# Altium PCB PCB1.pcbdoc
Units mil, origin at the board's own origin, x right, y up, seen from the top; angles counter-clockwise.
Board outline 6751.1 x 3505.43 mil, 4 copper layers (Top Layer, Inner1, Inner2, Bottom Layer); 50 components, 35 nets, 178 pads, 64 vias.
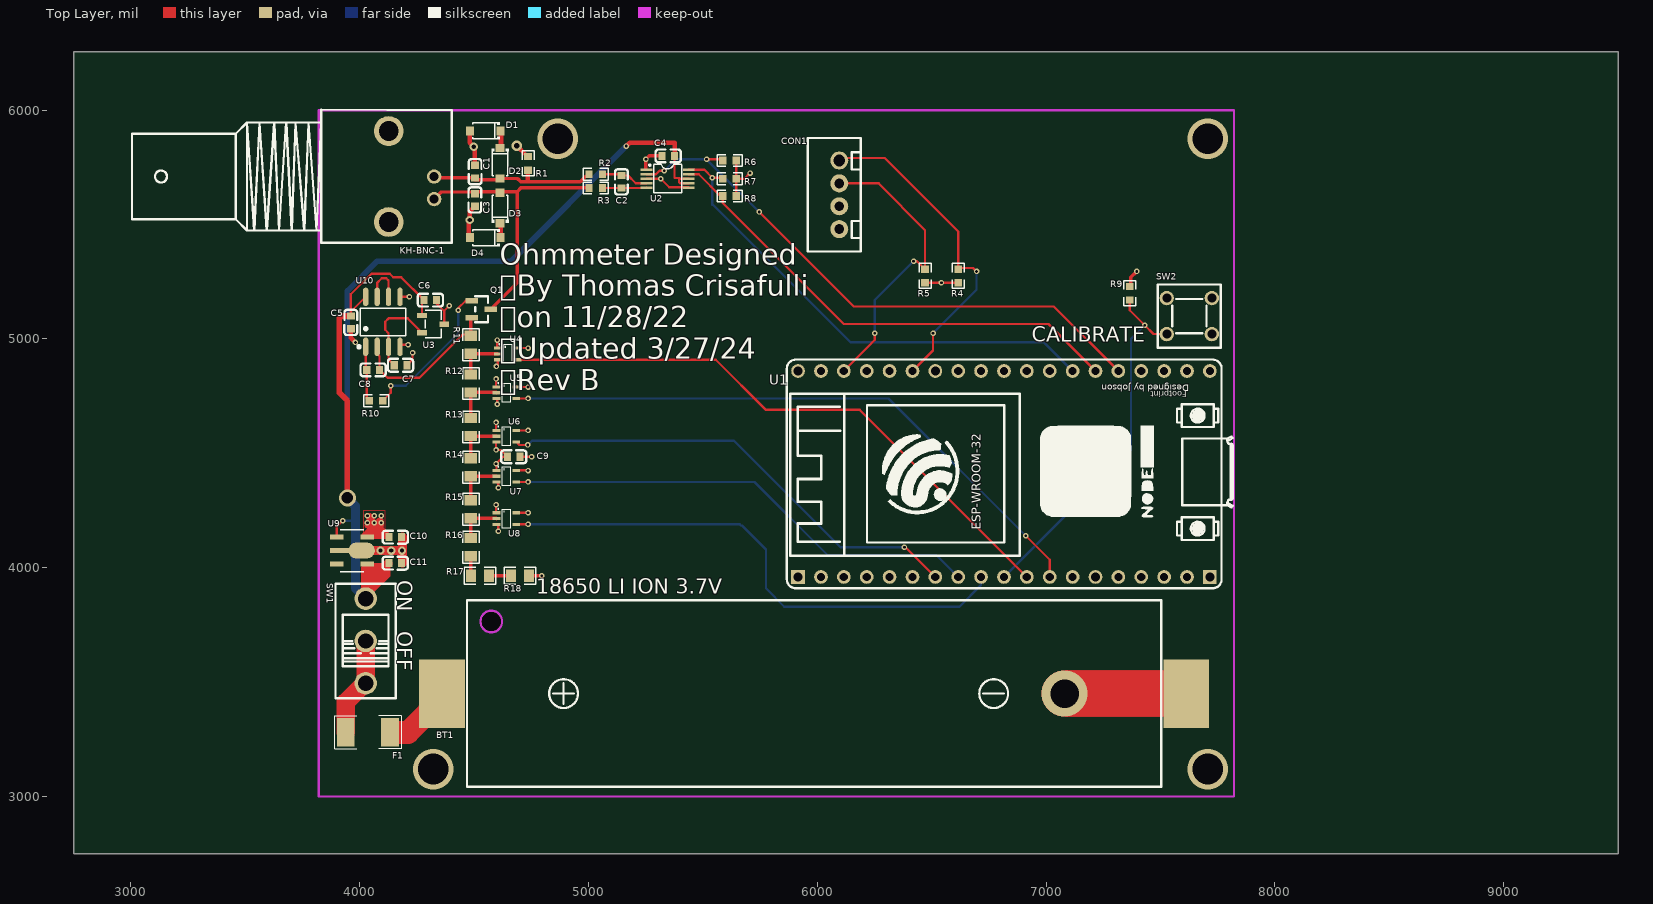
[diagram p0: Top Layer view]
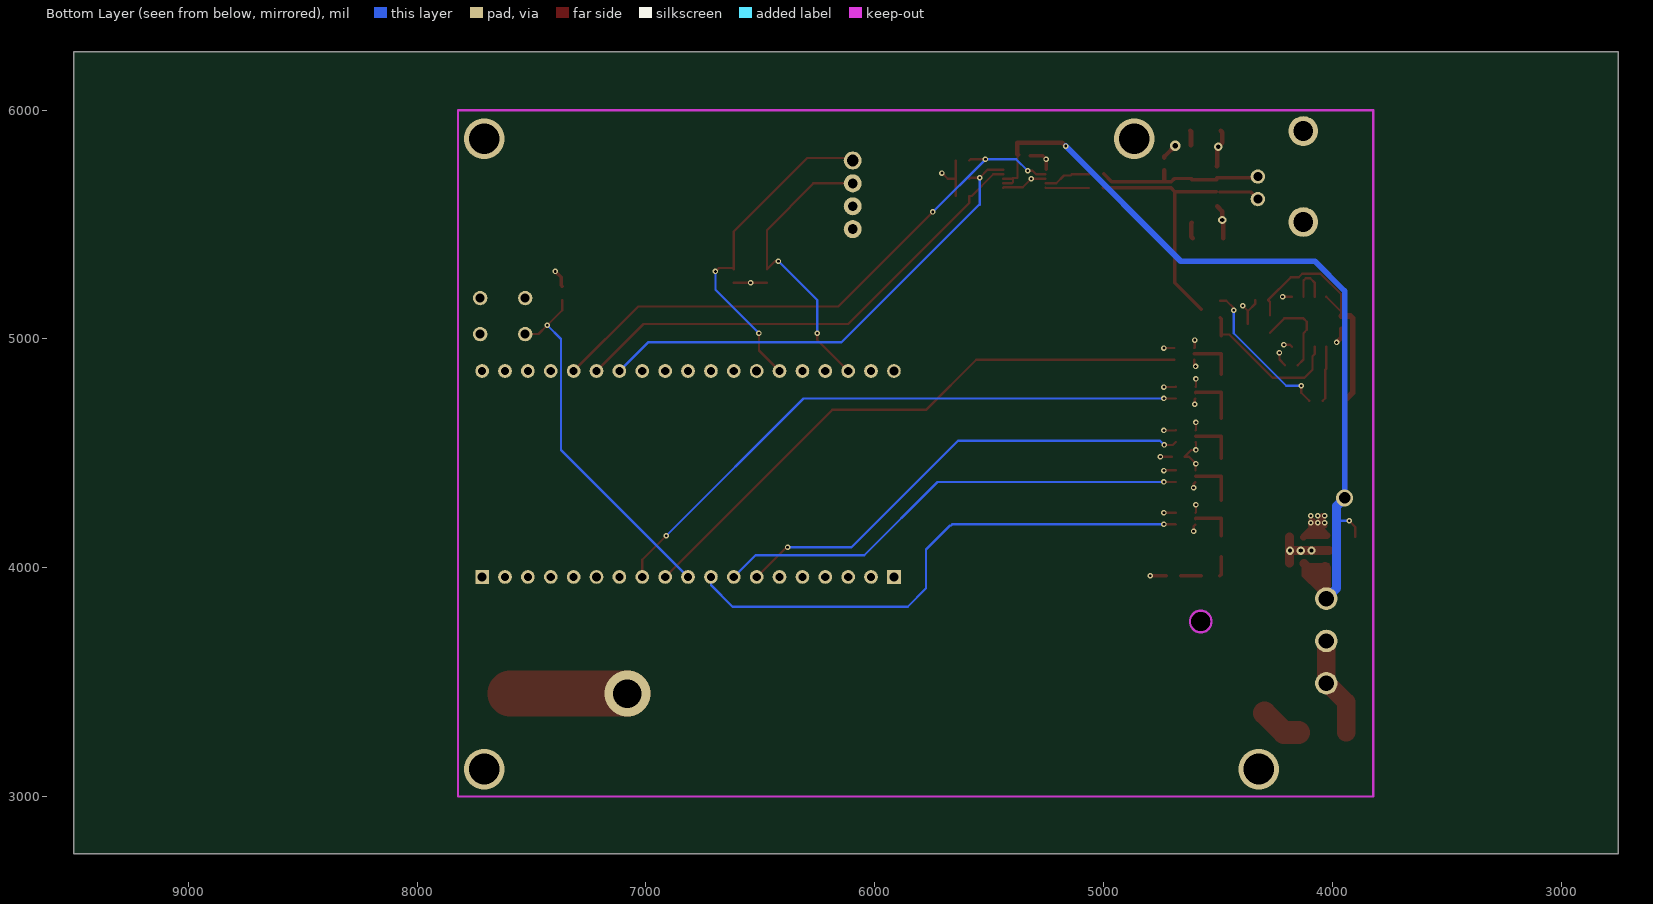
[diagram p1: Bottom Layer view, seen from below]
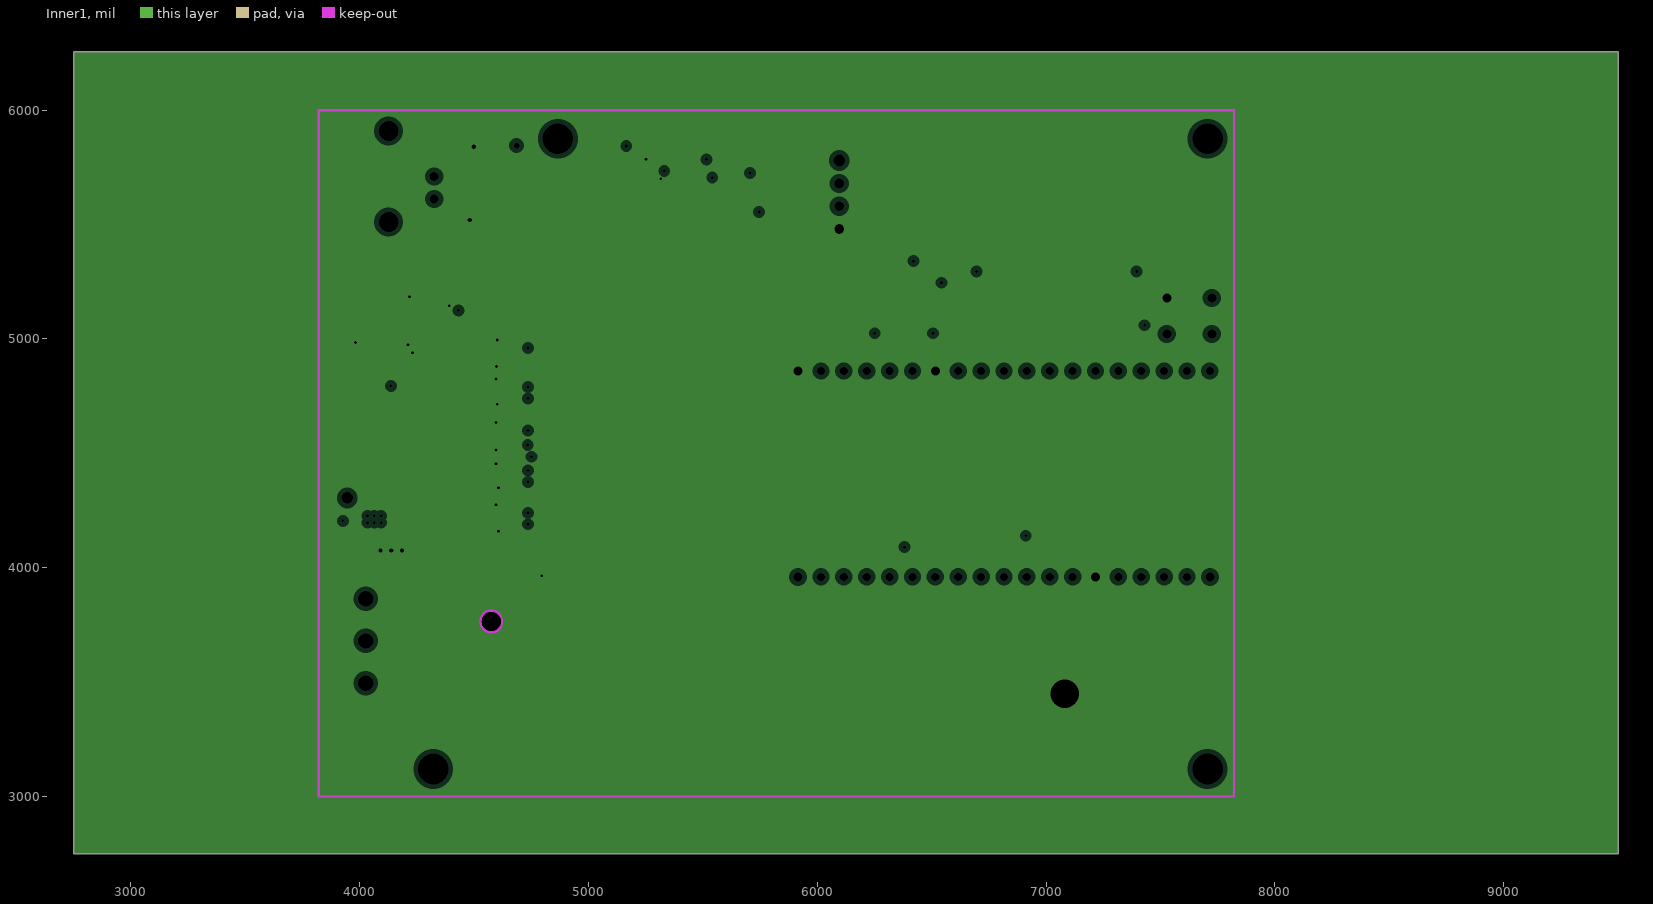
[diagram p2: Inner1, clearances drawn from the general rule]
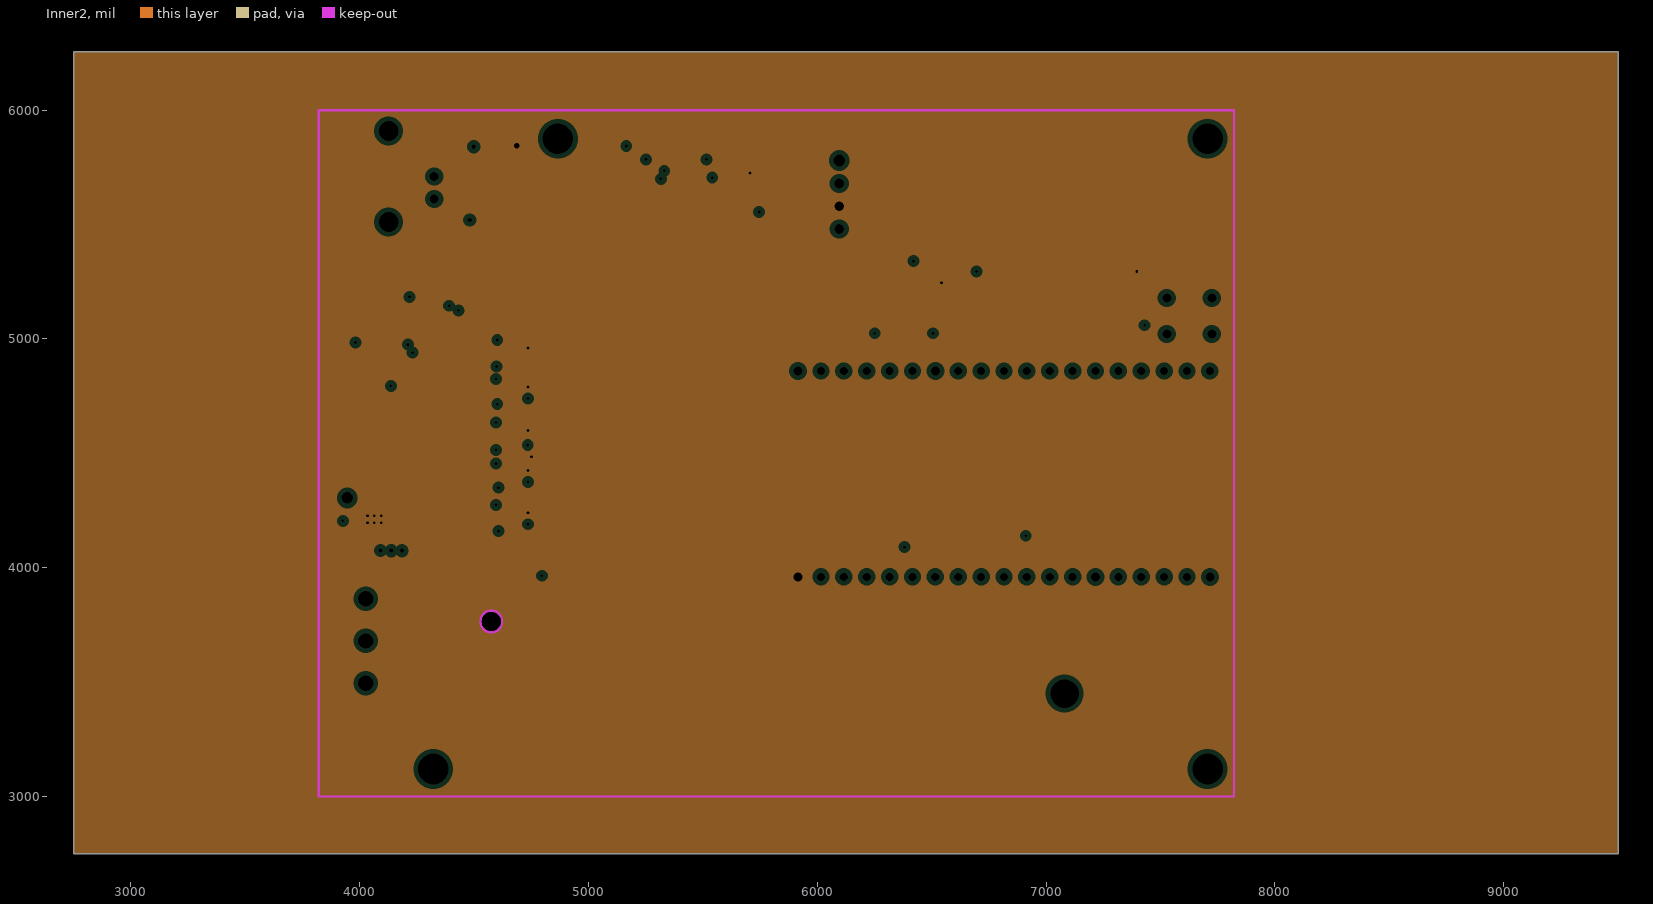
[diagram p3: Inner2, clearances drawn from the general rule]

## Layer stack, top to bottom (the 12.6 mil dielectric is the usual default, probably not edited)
Top Layer: signal copper (thickness not stored)
Dielectric: dielectric 12.6, FR-4, Dk 4.8
Inner1: plane copper (thickness not stored)
Dielectric: dielectric 12.6, FR-4, Dk 4.8
Inner2: plane copper (thickness not stored)
Dielectric: dielectric 12.6, FR-4, Dk 4.8
Bottom Layer: signal copper (thickness not stored)

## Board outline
9501.1,2750 2750,2750 2750,6255.43 9501.1,6255.43

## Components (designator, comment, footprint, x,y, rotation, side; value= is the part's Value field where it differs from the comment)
BT1 "BH-18650-B1BA002" BATTERY-SMD_18650-1S-L77.1-W20.7-1 5986.1,3450 r90 top
C1 "06031C103K4T2A" C0603 4504.6,5731.44 r90 top
C2 "CC0603KRX7R9BB104" C0603 5144.1,5687 r90 top
C3 "06031C103K4T2A" C0603 4503.6,5607.44 r270 top
C4 "CC0603KRX7R9BB104" C0603 5348.54,5800 r0 top
C5 "CC0603KRX7R9BB104" C0603 3961.1,5072.44 r90 top
C6 "CL10A106KP8NNNC" C0603 4308.54,5170 r180 top
C7 "CC0603KRX7R9BB104" C0603 4178.66,4885 r0 top
C8 "0603CG101F500NT" C0603 4058.66,4865 r0 top
C9 "CC0603KRX7R9BB104" C0603 4673.66,4485 r0 top
C10 "CL10A106KP8NNNC" C0603 4155.37,4133.54 r180 top
C11 "CL10A106KP8NNNC" C0603 4155.13,4020 r180 top
CON1 "XH2.54-4_C9900012082" CONN-TH_XH2.54-4 6096.1,5630 r90 top
D1 "PTVS30VS1UR,115" SOD-123_L2.6-W1.7-LS3.5-RD 4548.6,5910 r180 top
D2 "PTVS30VS1UR,115" SOD-123_L2.6-W1.7-LS3.5-RD 4613.6,5768 r270 top
D3 "PTVS30VS1UR,115" SOD-123_L2.6-W1.7-LS3.5-RD 4613.6,5572.5 r90 top
D4 "PTVS30VS1UR,115" SOD-123_L2.6-W1.7-LS3.5-RD 4548.6,5442.5 r180 top
F1 "0451.400MRL" 0451.400MRL 4171.1,3280 r180 top
KH-BNC-1 "KH-BNC75-3511" ANT-TH_KH-BNC75-3511 4226.1,5710 r270 top
Q1 "BSH105,215" TO-236AB_L2.9-W1.3-P0.95-LS2.3-BR 4531.1,5130 r180 top
R1 "AC0603FR-0710RL" R0603 4736.1,5767.5 r90 top
R2 "RS-03K2700FT" R0603 5031.44,5720 r0 top
R3 "RS-03K2700FT" R0603 5031.44,5660 r0 top
R4 "RMC06035.6K1%N" R0603 6616.1,5275.34 r90 top
R5 "RMC06035.6K1%N" R0603 6471.1,5275.34 r270 top
R6 "RMC06035.6K1%N" R0603 5616.44,5780 r0 top
R7 "RMC06035.6K1%N" R0603 5616.44,5700 r0 top
R8 "RMC06035.6K1%N" R0603 5616.44,5625 r0 top
R9 "RMC06035.6K1%N" R0603 7366.1,5199.66 r90 top
R10 "RMC06035.6K1%N" R0603 4071.44,4730 r180 top
R11 "RT0805BRB07100RL" R0805 4486.1,4974.37 r90 top
R12 "PTFR0805B620RN9" R0805 4486.1,4805 r90 top
R13 "PTFR0805B3K30N9" R0805 4486.1,4615 r90 top
R14 "PTFR0805B22K0N9" R0805 4486.1,4439.37 r90 top
R15 "PTFR0805B130KN9" R0805 4486.1,4255.63 r90 top
R16 "PTFR0805B270KN9" R0805 4486.1,4090 r90 top
R17 "PTFR0805B270KN9" R0805 4526.1,3965 r180 top
R18 "PTFR0805B270KN9" R0805 4701.1,3965 r180 top
SW1 "SS-12D10L4" SW-TH_SS-12D10L3 4026.1,3680 r90 top
SW2 "BTSA-N-P-11" SW-TH_BTSA-X-P-11 7626.1,5100 r0 top
U1 "ESP32" NODEMCU-32SLUA 6816.1,4410 r90 top
U2 "ADS1115IDGST" VSSOP-10_L3.0-W3.0-P0.50-LS4.9-BL 5346.1,5700 r270 top
U3 "REF3112AIDBZR" SOT-23-3_L2.9-W1.6-P1.90-LS2.8-BR 4321.1,5065 r180 top
U4 "MAX4715EXK+T" SC-70-5_L2.0-W1.3-P0.65-LS2.1-BR 4646.1,4935 r180 top
U5 "MAX4715EXK+T" SC-70-5_L2.0-W1.3-P0.65-LS2.1-BR 4641.1,4765 r180 top
U6 "MAX4715EXK+T" SC-70-5_L2.0-W1.3-P0.65-LS2.1-BR 4641.1,4575 r180 top
U7 "MAX4715EXK+T" SC-70-5_L2.0-W1.3-P0.65-LS2.1-BR 4641.1,4400 r180 top
U8 "MAX4715EXK+T" SC-70-5_L2.0-W1.3-P0.65-LS2.1-BR 4641.1,4215 r180 top
U9 "ME6217C33P5G" SOT-89-5_L4.5-W2.5-P1.50-LS4.5-BR 3966.1,4075 r180 top
U10 "OPA2365AIDR" SOIC-8_L4.9-W3.9-P1.27-LS6.0-BL 4101.1,5075 r0 top

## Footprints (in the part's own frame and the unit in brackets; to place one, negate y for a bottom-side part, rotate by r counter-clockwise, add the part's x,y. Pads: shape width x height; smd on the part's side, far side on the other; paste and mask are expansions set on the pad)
0451.400MRL [mm]
  rect 1.96x3.16 smd: 1(0.98,0) 2(5.89,0)
  silkscreen extent -0.26,-1.83 7.13,1.83
ANT-TH_KH-BNC75-3511 [mm]
  round 1.6 hole 1: 1(0,2.525) 2(2.5,2.525)
  round 3.3 hole 2.2: 3(5.05,-2.525) 4(-5.05,-2.525)
  silkscreen extent -7.44,-31.02 7.35,4.47
BATTERY-SMD_18650-1S-L77.1-W20.7-1 [mil]
  rect 300x200 smd: 1(0,-1626.5) 2(0,1626.5)
  Multi-Layer board cut-out: 314.96,1363.78 338.42,1370.23 355.56,1387.51 361.83,1411.02 355.56,1434.53 338.42,1451.81 314.96,1458.26 314.96,1458.26 291.5,1451.81 274.36,1434.53 268.09,1411.02 274.36,1387.51 291.5,1370.23 314.96,1363.78
  silkscreen extent -408,-1518 408,1518
C0603 [mm]
  rect 0.8x0.9 smd: 1(-0.7,0) 2(0.7,0)
  silkscreen extent -1.41,-0.71 1.39,0.72
CONN-TH_XH2.54-4 [mm]
  round 2 hole 1.1: 1(-3.81,0) 2(-1.27,0) 3(1.27,0)
  round 2 hole 1.3: 4(3.81,0)
  silkscreen extent -6.3,-2.4 6.3,3.5
NODEMCU-32SLUA [mil]
  rect 60x60 hole 39.37: 1(-450,-900) 19(-450,900)
  round 60 hole 36: 2(-450,-800) 3(-450,-700) 4(-450,-600) 5(-450,-500) 7(-450,-300) 8(-450,-200) 9(-450,-100) 10(-450,0) 11(-450,100) 12(-450,200) 13(-450,300) 14(-450,400) 15(-450,500) 16(-450,600) 17(-450,700) 18(-450,800) 20(450,-900) 21(450,-800) 22(450,-700) 23(450,-600) 24(450,-500) 25(450,-400) 26(450,-300) 27(450,-200) 28(450,-100) 29(450,0) 30(450,100) 31(450,200) 33(450,400) 34(450,500) 35(450,600) 36(450,700) 37(450,800)
  round 60 hole 39.37: 6(-450,-400) 32(450,300) 38(450,900)
  silkscreen extent -500,-999 500,949
R0603 [mil]
  rect 31.75x34.02 smd: 1(-29.66,0) 2(29.66,0)
  silkscreen extent -55,-26 55,26
R0805 [mm]
  rect 1.133x1.377 smd: 1(-1,0) 2(1,0)
  silkscreen extent -1.76,-0.92 1.76,0.92
SC-70-5_L2.0-W1.3-P0.65-LS2.1-BR [mm]
  rect 0.85x0.35 smd: 1(1.1,-0.65) 2(1.1,0) 3(1.1,0.65) 4(-1.1,0.65) 5(-1.1,-0.65)
  silkscreen extent -0.5,-1.12 0.96,1
SOD-123_L2.6-W1.7-LS3.5-RD [mm]
  rect 0.9x1 smd: 1(-1.692,0) 2(1.692,0)
  silkscreen extent -1.63,-0.94 1.41,0.94
SOIC-8_L4.9-W3.9-P1.27-LS6.0-BL [mm]
  oval 0.588x2.045 smd: 1(-1.905,-2.772) 2(-0.635,-2.772) 3(0.635,-2.772) 4(1.905,-2.772) 5(1.905,2.772) 6(0.635,2.772) 7(-0.635,2.772) 8(-1.905,2.772)
  silkscreen extent -2.8,-2.92 2.53,1.52
SOT-23-3_L2.9-W1.6-P1.90-LS2.8-BR [mm]
  rect 1.07x0.6 smd: 1(1.235,-0.95) 2(1.235,0.95) 3(-1.235,0)
  silkscreen extent -0.88,-1.54 0.88,1.54
SOT-89-5_L4.5-W2.5-P1.50-LS4.5-BR [mm]
  rect 1.5x0.574 smd: 1(1.697,-1.5) 3(1.697,1.5) 4(-1.697,1.5) 5(-1.697,-1.5)
  oval 2.94x1.76 smd: 2(-1.068,0)
  rect 2.209x0.552 smd: 2(1.343,0)
  silkscreen extent -1.3,-2.33 1.3,2.33
SW-TH_BTSA-X-P-11 [mm]
  round 1.6 hole 1: 1(-2.5,2) 2(-2.5,-2) 3(2.5,2) 4(2.5,-2)
  silkscreen extent -3.5,-3.5 3.5,3.5
SW-TH_SS-12D10L3 [mm]
  round 2.5 hole 1.7: 1(-4.7,0) 2(0,0) 3(4.7,0)
  silkscreen extent -6.35,-3.35 6.35,3.35
TO-236AB_L2.9-W1.3-P0.95-LS2.3-BR [mm]
  rect 1.4x0.6 smd: 1(1.05,-0.95) 2(1.05,0.95) 3(-1.05,0)
  silkscreen extent -0.75,-1.45 0.65,1.45
VSSOP-10_L3.0-W3.0-P0.50-LS4.9-BL [mm]
  rect 0.3x1.3 smd: 1(-1,-2.35) 2(-0.5,-2.35) 3(0,-2.35) 4(0.5,-2.35) 5(1,-2.35) 6(1,2.35) 7(0.5,2.35) 8(0,2.35) 9(-0.5,2.35) 10(-1,2.35)
  silkscreen extent -1.62,-2.08 1.52,1.54

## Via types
v1: diameter 24.02, hole 12.01, Top Layer to Bottom Layer, 42 vias
v2: diameter 24, hole 12, Top Layer to Bottom Layer, 10 vias
v3: diameter 36, hole 18, Top Layer to Bottom Layer, 5 vias
v4: diameter 177, hole 134, Top Layer to Bottom Layer, 4 vias
v5: diameter 75, hole 50, Top Layer to Bottom Layer, 1 vias
v6: diameter 200, hole 125, Top Layer to Bottom Layer, 1 vias
v7: diameter 45, hole 25, Top Layer to Bottom Layer, 1 vias

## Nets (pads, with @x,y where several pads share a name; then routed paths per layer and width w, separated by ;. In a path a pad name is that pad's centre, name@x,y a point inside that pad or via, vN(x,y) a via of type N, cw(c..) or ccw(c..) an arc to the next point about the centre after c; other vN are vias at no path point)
1.250V: C7.1 U3.2 U10.3 | length 400
  Top Layer w10: C7.1 4126.1,4910 U10.3 4126.1,5025 4111.1,5040 4111.1,5075 4126.1,5090 4210.08,5090 U3.2
3V3: C9.2 C10.2 CON1.2 R1.2 R4.1 R5.2 R6.2 R7.2 R8.2 R9.2 U1.19 U4.5 U5.5 U6.5 U7.5 U8.5 U9.5 | length 1248.4
  Top Layer w10: U8.5 4685,4240 v1(4736.1,4240) ; U7.5 4735.51,4425.59 v1(4736.1,4425) ; U6.5 4685,4600 v1(4736.1,4600) ; U5.5 4685,4790 v1(4736.1,4790) ; U4.5 4735.51,4960.59 v1(4736.1,4960) ; C9.2 v1(4751.1,4485) ; R8.2 R7.2 ; R6.2 R7.2 ; v1(5706.1,5725) 5681.1,5700 R7.2 ; R5.2 v1(6542.96,5245.68) R4.1
  Top Layer w15: R9.2 7371.1,5234.32 7371.1,5270 v1(7396.1,5295)
  Top Layer w20: v7@4682.35,5848.75 4733.6,5797.5 R1.2@4733.6,5793.09
  Top Layer w25: 4033.6,4184.23 4046.1,4196.73 ; v1(4033.6,4196.73) 4046.1,4196.73 ; 4060.43,4152.4 4093.6,4185.57 v1(4093.6,4196.73) ; v1(4063.6,4196.73) 4051.1,4196.73 4048.6,4199.23 4046.1,4196.73
  Top Layer w30: U9.5@4023.69,4140.98 C10.2@4119.37,4140.98 ; U9.5@4033.78,4139.56 4033.78,4151.07 v1@4089.58,4206.87 ; v1@4043.6,4224.23 4043.6,4215.25 C10.2@4125.31,4133.54
  other v1: 4033.6,4226.73 4063.6,4226.73 4093.6,4226.73
  other v7: 4686.1,5845
$1N34949: D1.1 D2.1 | length 65
  Top Layer w20: D2.1@4618.6,5846.63 4617.47,5847.76 4617.47,5907.24 D1.1@4620.23,5910
$1N40044: D3.1 D4.1 | length 72.4
  Top Layer w20: D4.1@4610.23,5440 4616.77,5446.54 4616.77,5505.2 D3.1@4613.6,5508.37
$1N64285: C1.1 D2.2 KH-BNC-1.1 R1.1 R2.1 | length 736.4
  Top Layer w15: KH-BNC-1.1 4331.63,5703.88 C1.1 ; C1.1@4504.6,5695.43 D2.2@4613.6,5695.43 ; D2.2 4689.73,5701.37 4703.6,5687.5 4964.95,5687.5 R2.1@4998.7,5721.25
  Top Layer w20: 4733.6,5696.9 R1.1@4733.6,5737.84
$4N526: Q1.1 R10.1 | length 651.8
  Top Layer w10: R10.1 4136.1,4765 v2(4136.1,4795) ; v2(4431.1,5125) 4431.1,5135 4463.5,5167.4 Q1.1
  Bottom Layer w10: v2(4136.1,4795) 4201.1,4795 4431.1,5025 v2(4431.1,5125)
$4N529: C8.1 R10.2 U10.1 | length 242.3
  Top Layer w10: U10.1 4026.1,4870 C8.1 4031.1,4740.68 R10.2
$4N533: U10.6 U10.7 | length 194.1
  Top Layer w10: U10.7 4076.1,5245 4096.1,5265 4116.1,5265 4126.1,5255 U10.6
$4N538: C8.2 Q1.2 R11.2 U10.2 | length 680.5
  Top Layer w10: U10.2 4076.1,4935 4086.22,4924.88 C8.2 4121.22,4830 4261.1,4830 4450.42,5019.32 4480.52,5019.32 R11.2
  Top Layer w15: R11.2 4486.1,5088.94 Q1.2
$4N2969: R16.1 R17.2 | length 84.8
  Top Layer w15: R16.1@4486.1,4047.78 4486.1,3970 R17.2@4491.1,3965
$4N2970: R17.1 R18.2 | length 88.4
  Top Layer w15: R17.1@4573.33,3965 R18.2
$4N2972: R15.1 R16.2 U8.2 | length 188.5
  Top Layer w15: R16.2@4486.1,4140 R15.1 4596.53,4216.26 U8.2
$4N2973: R13.1 R14.2 U6.2 | length 208
  Top Layer w15: R14.2 4486.1,4575 U6.2
$4N2979: R14.1 R15.2 U7.2 | length 216.7
  Top Layer w15: R15.2 R14.1 U7.2
$4N2983: R12.1 R13.2 U5.2 | length 224.7
  Top Layer w15: R13.2@4486.1,4653.74 4486.1,4766.26 4596.53,4766.26 U5.2
$4N3047: R11.1 R12.2 U4.2 | length 206.7
  Top Layer w15: R12.2@4486.1,4845 R11.1 U4.2
$6N1642: BT1.2 F1.1 | length 183.8
  Top Layer w100: F1.1@4147.47,3280 4211.1,3280 BT1.2@4296.1,3365
$6N1643: F1.2 SW1.1 SW1.2 | length 435.6
  Top Layer w80: F1.2 3939.21,3413.04 4026.83,3500.66 SW1.2@4026.83,3679.27
ADC_AIN0: C2.2 R2.2 U2.4 | length 207.3
  Top Layer w10: R2.2@5062.74,5720 5138.66,5720 C2.2 5173.02,5714.56 5206.89,5680.69 5253.21,5680.69 U2.4
ADC_AIN1: C2.1 R3.2 U2.5 | length 191.4
  Top Layer w10: R3.2@5062.94,5660 5143.54,5660 C2.1 5252.4,5659.44 U2.5
ADC_I2C_ALERT_RDY: R6.1 U1.24 U2.2 | length 2545.5
  Top Layer w10: U2.2 5294.76,5719.69 5310.08,5735 v2(5331.1,5735) ; v2(5516.1,5785) 5581.78,5785 R6.1 ; v2(5746.1,5555) 6159.1,5142 7034.1,5142 U1.24
  Bottom Layer w10: v2(5331.1,5735) 5381.1,5785 v2(5516.1,5785) v2(5746.1,5555)
ADC_I2C_SCL: R7.1 U1.26 U2.10 | length 2158.9
  Top Layer w10: U2.10 5506.73,5739.38 v1(5541.1,5705) 5581.78,5705 R7.1
  Bottom Layer w10: v1(5541.1,5705) 5541.1,5586.51 5544.59,5586.51 6146.1,4985 6991.1,4985 U1.26
ADC_I2C_SDA: R8.1 U1.25 U2.9 | length 2151.5
  Top Layer w10: U2.9 5481.42,5719.69 5576.1,5625 R8.1 5586.78,5594.32 6116.1,5065 7011.1,5065 U1.25
CALIBRATE: R9.1 SW2.2 U1.10 | length 1604.3
  Top Layer w10: R9.1 7366.1,5125 v1(7431.1,5060) 7469.84,5021.26 SW2.2
  Bottom Layer w10: U1.10 7371.1,4515 7371.1,5000 v1(7431.1,5060)
CURRENT_SINK_IN: C3.1 D3.2 KH-BNC-1.2 Q1.3 R3.1 | length 1242.6
  Top Layer w15: KH-BNC-1.2 4356.44,5642.5 C3.1@4491.1,5642.5 ; C3.1@4506.1,5643.94 4506.3,5644.13 4616.1,5644.13 4687.73,5644.13 ; Q1.3 4687.73,5245.29 4687.73,5644.13 ; R3.1 4703.6,5660 4687.73,5644.13
GND: BT1.1 C1.2 C3.2 C4.1 C5.1 C6.1 C7.2 C9.1 C10.1 C11.1 CON1.1 D1.2 D4.2 R18.1 SW2.1 U1.6 U1.32 U1.38 U2.1 U2.3 U2.6 U3.3 U4.1 U4.3 U5.1 U5.3 U6.1 U6.3 U7.1 U7.3 U8.1 U8.3 U9.2 U10.4 U10.5 | length 2318.3
  Top Layer w10: U10.4 4185.25,4975 v1(4211.1,4975) ; U10.5 v2(4217.51,5184.15) ; C7.2 4231.1,4909.88 v1(4231.1,4940) ; C6.1 4336.1,5155 4369.73,5121.38 ; U3.3 4369.73,5121.38 ; v2(4391.1,5145) 4369.73,5123.62 4369.73,5121.38 ; v1(4596.1,4275) 4596.1,4242.28 U8.1 ; v1(4596.1,4635) 4596.1,4602.28 U6.1 ; v1(4596.1,4825) 4596.1,4792.28 U5.1 ; U8.3 4606.1,4181.1 v1(4606.1,4160) ; U7.3 4606.1,4366.1 v1(4606.1,4350) ; U7.1 4597.79,4453.31 v1(4596.1,4455) 4626.1,4485 C9.1 4616.1,4515 v1(4596.1,4515) 4596.1,4547.72 U6.3 ; U5.3 4601.1,4736.1 v1(4601.1,4715) ; v1(4597.79,4880) 4602.79,4885 U4.3 ; v1(4601.1,4995) 4601.1,4962.28 U4.1 ; U2.3 v1(5316.1,5700) 5352.69,5663.41 5435.85,5663.41 U2.6
  Top Layer w15: R18.1@4724.84,3965 v1(4796.1,3965) ; U2.1@5251.1,5741.85 v1(5251.1,5785) 5266.1,5800 C4.1
  Top Layer w20: C5.1 3961.1,5005 v2(3981.1,4985) ; D4.2@4476.97,5440 4476.97,5515.87 v3(4481.1,5520) 4481.1,5557.38 C3.2 ; D1.2@4486.97,5910 4481.1,5904.13 4481.1,5857.5 4503.6,5835 4503.6,5756 C1.2@4504.6,5755
  Top Layer w40: U9.2@4014.93,4074.97 v3(4184.63,4074.66) ; C10.1@4186.56,4133.65 4186.62,4074.97 C11.1@4186.62,4020
  Top Layer w200: v6(7081.1,3450) BT1.1@7592.6,3450
  other v3: 4090.93,4075.02 4137.6,4074.66 4498.6,5840
OLED_I2C_SCL: CON1.3 R5.1 U1.36 | length 1301.7
  Top Layer w10: CON1.3 6269.18,5680 6471.1,5475 R5.1 6436.1,5340 v1(6421.1,5340) ; U1.36 6251.1,4995 v1(6251.1,5025)
  Bottom Layer w10: v1(6251.1,5025) 6251.1,5170 v1(6421.1,5340)
OLED_I2C_SDA: CON1.4 R4.2 U1.33 | length 1461.8
  Top Layer w10: CON1.4 6107.1,5791 6295.1,5791 6616.1,5470 R4.2 6621.1,5310 6681.1,5310 v1(6696.1,5295) ; U1.33 6506.1,4950 v1(6506.1,5025)
  Bottom Layer w10: v1(6506.1,5025) 6696.1,5215 v1(6696.1,5295)
RANGE_SW_1: U1.9 U4.4 | length 2619.9
  Top Layer w10: U4.4 5366.69,4909.41 5556.69,4909.41 5776.1,4690 6041.1,4690 6185.55,4690 6915.55,3960 U1.9
RANGE_SW_2: U1.8 U5.4 | length 2699
  Top Layer w10: U5.4 4735.51,4739.41 v1(4736.1,4740) ; v1(6911.1,4140) 7016.1,4035 U1.8
  Bottom Layer w10: v1(4736.1,4740) 6311.1,4740 v1(6911.1,4140)
RANGE_SW_3: U1.13 U6.4 | length 2090.9
  Top Layer w10: U6.4 4696.97,4536.85 v1(4734.47,4536.85) ; v1(6381.1,4090) 6386.1,4090 U1.13
  Bottom Layer w10: v1(4734.47,4536.85) 4752.62,4555 5636.1,4555 6101.1,4090 v1(6381.1,4090)
RANGE_SW_4: U1.12 U7.4 | length 2103.8
  Top Layer w10: U7.4 4685,4375 v1(4736.1,4375)
  Bottom Layer w10: v1(4736.1,4375) 5726.1,4375 6046.1,4055 6521.1,4055 U1.12
RANGE_SW_5: U1.11 U8.4 | length 2355
  Top Layer w10: U8.4 4685,4190 v1(4736.1,4190)
  Bottom Layer w10: v1(4736.1,4190) 5661.1,4190 5666.1,4185 5671.1,4185 5776.1,4080 5776.1,3910 5856.1,3830 6621.1,3830 6716.1,3925 U1.11
VBAT: C4.2 C5.2 C6.2 C11.2 SW1.3 U2.7 U2.8 U3.1 U9.1 U9.4 U10.8 | length 5343.1
  Top Layer w10: U9.1 3899.27,4178.17 v2(3926.1,4205) ; C5.2 3961.1,5119.15 ; U10.8 3961.1,5119.15 ; U3.1 4272.48,5161.49 C6.2 4180.98,5270 4146.1,5270 4131.1,5285 4051.1,5285 3961.1,5195 3961.1,5119.15 ; C4.2 5376.1,5703.22 5396.03,5703.22 ; U2.7 5400.79,5680.31 5396.03,5685.07 5396.03,5699.99 ; U2.8 5399.26,5699.99 ; 5396.03,5699.99 5399.26,5699.99 ; 5396.03,5699.99 5396.03,5703.22 ; 5396.03,5703.22 5399.26,5699.99
  Top Layer w20: v2(5165.1,5843) 5179.6,5857.5 5376.1,5857.5 5376.1,5807.5 C4.2@5373.6,5805
  Top Layer w25: v5(3946.1,4305) 3946.1,4730 3931.1,4745 3911.1,4765 3911.1,5090 3921.1,5100 C5.2
  Top Layer w40: U9.4@4031.1,4005 4026.1,4000 SW1.3 4026.1,3913.04 C11.2@4122.98,4018.37
  Bottom Layer w10: v2(3926.1,4205) 3981.1,4205
  Bottom Layer w25: v5(3946.1,4305) 3946.1,5210 4076.1,5340 4662.1,5340 v2(5165.1,5843)
  Bottom Layer w40: v5(3946.1,4305) 3981.1,4270 3981.1,3910.04 SW1.3
"": KH-BNC-1.3 KH-BNC-1.4 SW2.3 SW2.4 U1.1 U1.2 U1.3 U1.4 U1.5 U1.7 U1.14 U1.15 U1.16 U1.17 U1.18 U1.20 U1.21 U1.22 U1.23 U1.27 U1.28 U1.29 U1.30 U1.31 U1.34 U1.35 U1.37 U9.3
  other v4: 4321.1,3120 7706.1,3120 4866.1,5875 7706.1,5875

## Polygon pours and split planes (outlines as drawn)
3V3 on Top Layer (solid, pour order 0): 4111.1,4249.23 4016.1,4249.23 4016.1,4137.9 4111.1,4137.9
GND on Top Layer (solid, remove dead copper, pour order 2): 7081.1,3350 7561.1,3350 7561.1,3550 7081.1,3550
GND on Inner1 (split plane): 3831.2,3010.1 3831.2,5989.9 7811,5989.9 7811,3010.1
GND on Inner1 (split plane): 6101.1,5480 6101.1,5430.43 6091.1,5430.43 6091.1,5480
GND on Inner1 (split plane): 6046.53,5485 6096.1,5485 6096.1,5475 6046.53,5475
GND on Inner1 (split plane): 6096.1,5485 6145.67,5485 6145.67,5475 6096.1,5475
GND on Inner1 (split plane): 5921.1,4860 5921.1,4819.8 5911.1,4819.8 5911.1,4860
GND on Inner1 (split plane): 5911.1,4860 5911.1,4900.2 5921.1,4900.2 5921.1,4860
GND on Inner1 (split plane): 5875.9,4865 5916.1,4865 5916.1,4855 5875.9,4855
GND on Inner1 (split plane): 5916.1,4865 5956.3,4865 5956.3,4855 5916.1,4855
GND on Inner1 (split plane): 6521.1,4860 6521.1,4819.8 6511.1,4819.8 6511.1,4860
GND on Inner1 (split plane): 6511.1,4860 6511.1,4900.2 6521.1,4900.2 6521.1,4860
GND on Inner1 (split plane): 6475.9,4865 6516.1,4865 6516.1,4855 6475.9,4855
GND on Inner1 (split plane): 6516.1,4865 6556.3,4865 6556.3,4855 6516.1,4855
GND on Inner1 (split plane): 7221.1,3960 7221.1,3919.8 7211.1,3919.8 7211.1,3960
GND on Inner1 (split plane): 7211.1,3960 7211.1,4000.2 7221.1,4000.2 7221.1,3960
GND on Inner1 (split plane): 7175.9,3965 7216.1,3965 7216.1,3955 7175.9,3955
GND on Inner1 (split plane): 7216.1,3965 7256.3,3965 7256.3,3955 7216.1,3955
GND on Inner1 (split plane): 7485.98,5183.74 7527.68,5183.74 7527.68,5173.74 7485.98,5173.74
GND on Inner1 (split plane): 7527.68,5183.74 7569.37,5183.74 7569.37,5173.74 7527.68,5173.74
GND on Inner1 (split plane): 7522.68,5178.74 7522.68,5220.44 7532.68,5220.44 7532.68,5178.74
GND on Inner1 (split plane): 7532.68,5178.74 7532.68,5137.04 7522.68,5137.04 7522.68,5178.74
3V3 on Inner2 (split plane): 3831.2,3010.1 3831.2,5989.9 7811,5989.9 7811,3010.1
3V3 on Inner2 (split plane): 6046.53,5585 6096.1,5585 6096.1,5575 6046.53,5575
3V3 on Inner2 (split plane): 6096.1,5585 6145.67,5585 6145.67,5575 6096.1,5575
3V3 on Inner2 (split plane): 5921.1,3960 5921.1,3919.8 5911.1,3919.8 5911.1,3960
3V3 on Inner2 (split plane): 5911.1,3960 5911.1,4000.2 5921.1,4000.2 5921.1,3960
3V3 on Inner2 (split plane): 5875.9,3965 5916.1,3965 5916.1,3955 5875.9,3955
3V3 on Inner2 (split plane): 5916.1,3965 5956.3,3965 5956.3,3955 5916.1,3955

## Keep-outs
Board Outline Layer:
  lines w10 net "": 3821.1,3000 7821.1,3000 7821.1,6000 3821.1,6000 3821.1,3000
Multi-Layer:
  circle w10: c4575.08,3764.96 r47.24

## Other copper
Top Layer:
  region net VBAT: 4012.99,4019.94 4132.97,4019.94 4011.42,3897.98
  region net VBAT: 4132.61,4019.57 4016.01,3902.97 4016.01,3876.41 4033.68,3894.08 4064.14,3894.08 4132.61,3962.55

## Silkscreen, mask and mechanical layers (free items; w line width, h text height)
Top Silkscreen Layer:
  text "CALIBRATE" at 6938.46,4987.2 h64.9
  text "Ohmmeter Designed  /  By Thomas Crisafulli /  on 11/28/22 /  Updated 3/27/24  /  Rev B" at 4613.17,4776.64 h91.42
  text "Footprint" at 7615.16,4771.12 h25.96 r180
  text "ON   OFF" at 4163.3,3944.79 h64.9 r270
  text "18650 LI ION 3.7V" at 4770.66,3887.2 h64.9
